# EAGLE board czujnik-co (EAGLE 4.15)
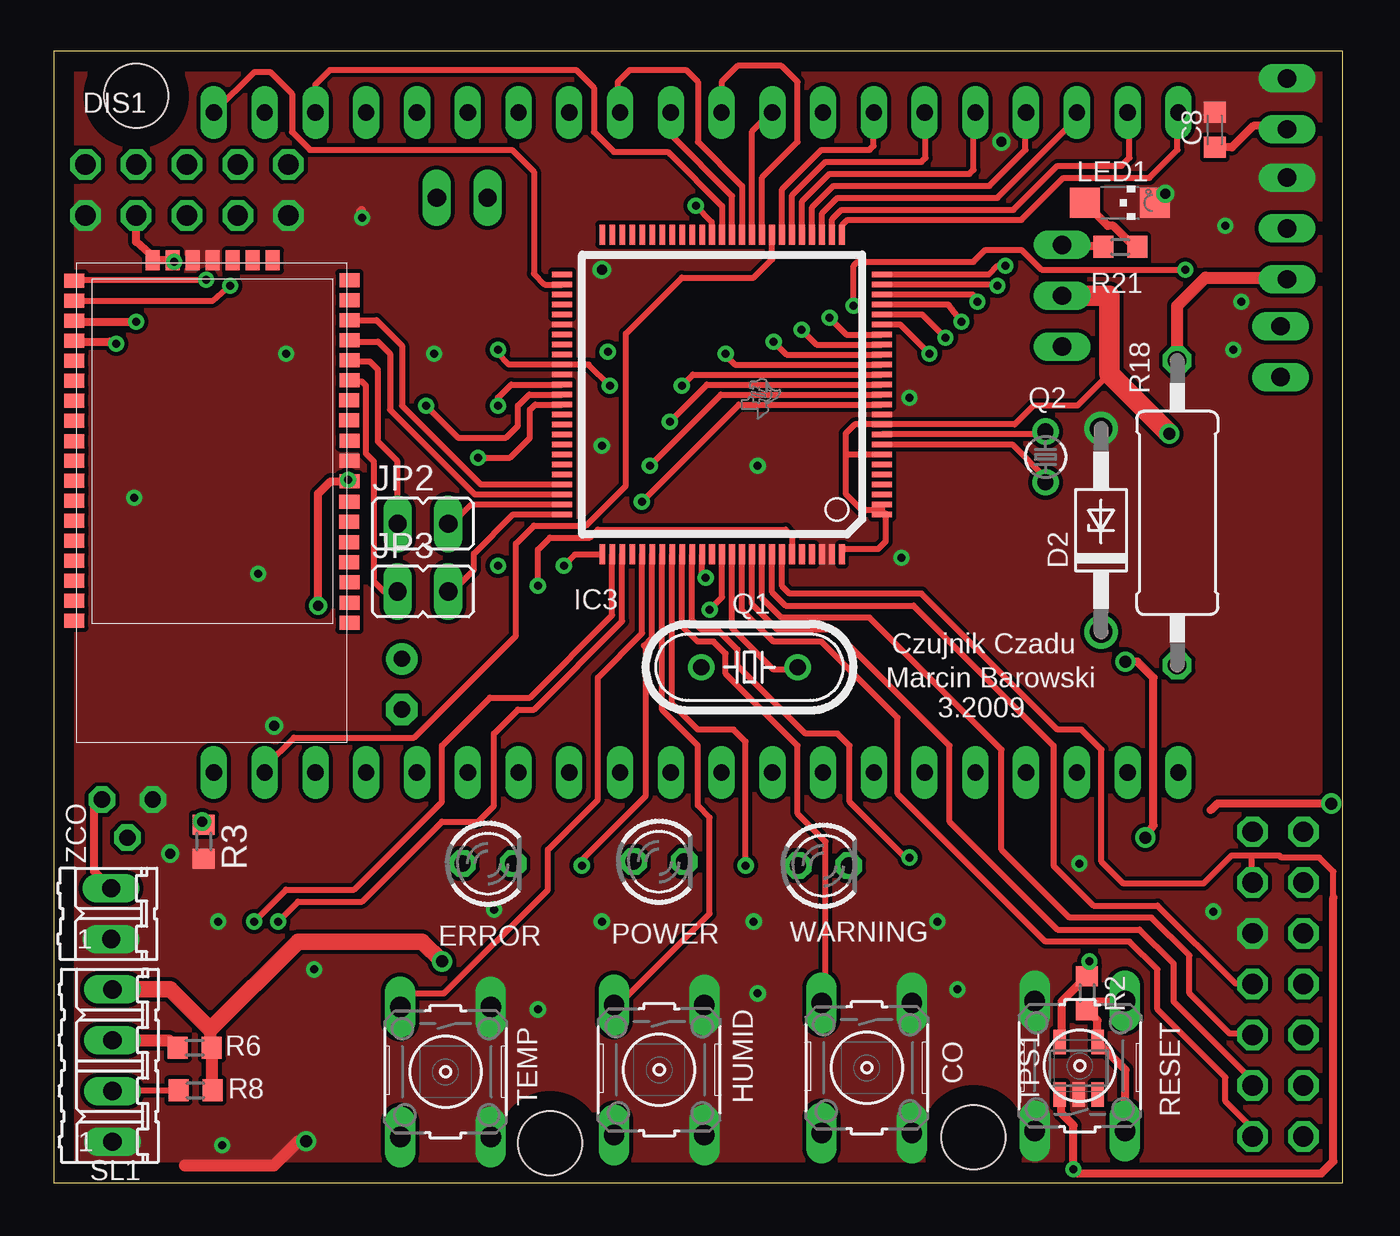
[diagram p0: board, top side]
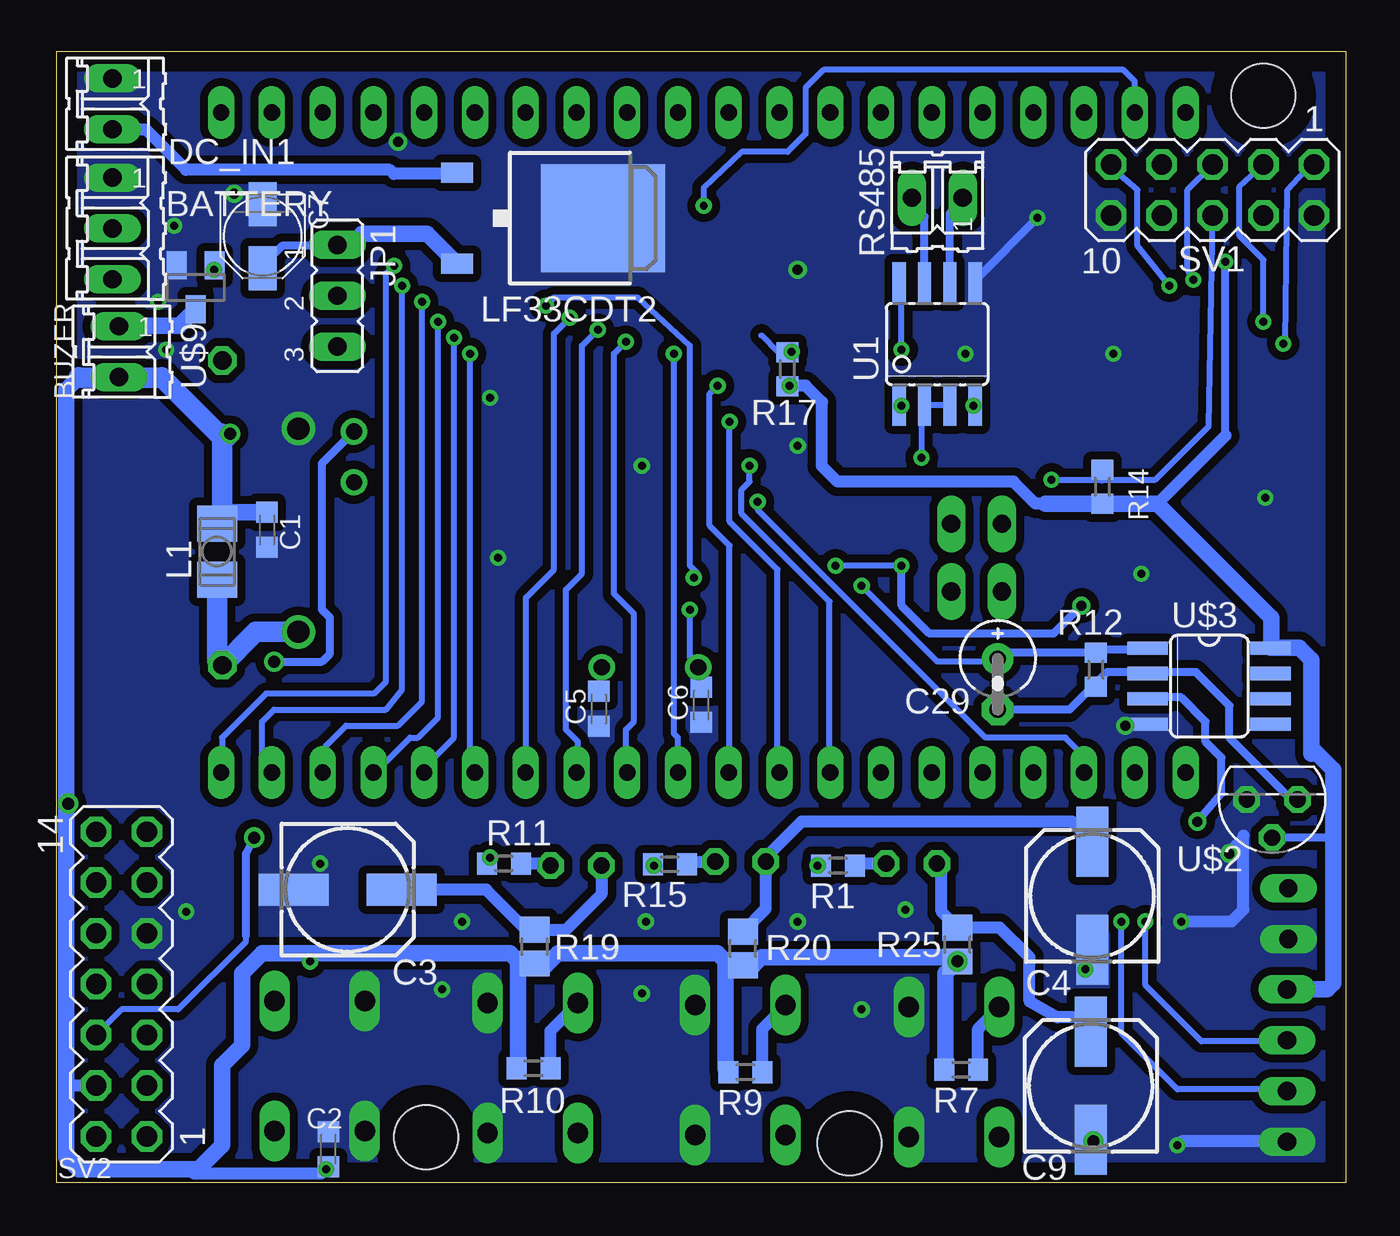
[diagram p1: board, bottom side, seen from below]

Size 64.5 x 56.6 mm. Coordinates in mm from the lower left corner, seen from the top.
Outline: 0,0 64.5,0 64.5,56.6 0,56.6 0,0
Copper layers (1*16): Top 0.035mm / dielectric 1.5mm / Bottom 0.035mm
Design rules "default": minimum track width 10mil, minimum drill 24mil, track to track 8mil, track to pad 8mil, pad to pad 8mil, via to via 8mil, smd to smd 8mil, copper to edge 40mil, drill to drill 8mil, minimum pad ring 10mil, minimum via ring 8mil, stop-mask expansion 4mil, vias tented up to drill 0mil, thermal gap 10mil
Holes 3.2 mm at 4.13,54.37 46.03,2.27 24.83,1.97

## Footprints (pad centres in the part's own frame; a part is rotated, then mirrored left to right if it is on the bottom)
03P = drill 0.914 long: 1 -2.54,0; 2 0,0; 3 2.54,0
02P = drill 0.914 long: 1 -1.27,0; 2 1.27,0
C0603K = smd 1.05 x 1.08: 1 -0.875,0; 2 0.875,0
153CLV-0605 = smd 3.5 x 1.6: + 2.7,0; - -2.7,0
PANASONIC_B = smd 2.2 x 1.4: + 1.6,0; - -1.6,0
E2,5RE = drill 0.813 pad 1.575 round: + -1.27,0 | drill 0.813 pad 1.575 octagon: - 1.27,0
B3F-10XX = drill 1.016 long: 1 -3.251,2.261; 2 3.251,2.261; 3 -3.251,-2.261; 4 3.251,-2.261
DO41Z10 = drill 1.118 round: A 5.08,0; C -5.08,0
H1331C = drill 0.813 long: 1 -24.13,-16.51; 2 -21.59,-16.51; 3 -19.05,-16.51; 4 -16.51,-16.51; 5 -13.97,-16.51; 6 -11.43,-16.51; 7 -8.89,-16.51; 8 -6.35,-16.51; 9 -3.81,-16.51; 10 -1.27,-16.51; 11 1.27,-16.51; 12 3.81,-16.51; 13 6.35,-16.51; 14 8.89,-16.51; 15 11.43,-16.51; 16 13.97,-16.51; 17 16.51,-16.51; 18 19.05,-16.51; 19 21.59,-16.51; 20 24.13,-16.51; 21 24.13,16.51; 22 21.59,16.51; 23 19.05,16.51; 24 16.51,16.51; 25 13.97,16.51; 26 11.43,16.51; 27 8.89,16.51; 28 6.35,16.51; 29 3.81,16.51; 30 1.27,16.51; 31 -1.27,16.51; 32 -3.81,16.51; 33 -6.35,16.51; 34 -8.89,16.51; 35 -11.43,16.51; 36 -13.97,16.51; 37 -16.51,16.51; 38 -19.05,16.51; 39 -21.59,16.51; 40 -24.13,16.51
LED3MM = drill 0.813 octagon: A -1.27,0; K 1.27,0
S-PQFP-G100(PZ) = smd 0.29 x 1: 1 -6,-8; 2 -5.5,-8; 3 -5,-8; 4 -4.5,-8; 5 -4,-8; 6 -3.5,-8; 7 -3,-8; 8 -2.5,-8; 9 -2,-8; 10 -1.5,-8; 11 -1,-8; 12 -0.5,-8; 13 0,-8; 14 0.5,-8; 15 1,-8; 16 1.5,-8; 17 2,-8; 18 2.5,-8; 19 3,-8; 20 3.5,-8; 21 4,-8; 22 4.5,-8; 23 5,-8; 24 5.5,-8; 25 6,-8; 51 6,8; 52 5.5,8; 53 5,8; 54 4.5,8; 55 4,8; 56 3.5,8; 57 3,8; 58 2.5,8; 59 2,8; 60 1.5,8; 61 1,8; 62 0.5,8; 63 0,8; 64 -0.5,8; 65 -1,8; 66 -1.5,8; 67 -2,8; 68 -2.5,8; 69 -3,8; 70 -3.5,8; 71 -4,8; 72 -4.5,8; 73 -5,8; 74 -5.5,8; 75 -6,8 | smd 1 x 0.29: 26 8,-6; 27 8,-5.5; 28 8,-5; 29 8,-4.5; 30 8,-4; 31 8,-3.5; 32 8,-3; 33 8,-2.5; 34 8,-2; 35 8,-1.5; 36 8,-1; 37 8,-0.5; 38 8,0; 39 8,0.5; 40 8,1; 41 8,1.5; 42 8,2; 43 8,2.5; 44 8,3; 45 8,3.5; 46 8,4; 47 8,4.5; 48 8,5; 49 8,5.5; 50 8,6; 76 -8,6; 77 -8,5.5; 78 -8,5; 79 -8,4.5; 80 -8,4; 81 -8,3.5; 82 -8,3; 83 -8,2.5; 84 -8,2; 85 -8,1.5; 86 -8,1; 87 -8,0.5; 88 -8,0; 89 -8,-0.5; 90 -8,-1; 91 -8,-1.5; 92 -8,-2; 93 -8,-2.5; 94 -8,-3; 95 -8,-3.5; 96 -8,-4; 97 -8,-4.5; 98 -8,-5; 99 -8,-5.5; 100 -8,-6
JP2 = drill 0.914 long: 1 -2.54,0; 2 0,0; 3 2.54,0
JP1 = drill 0.914 long: 1 0,-1.27; 2 0,1.27
L3225P = smd 1.8 x 2: 1 -1.4,0; 2 1.4,0
CHIPLED_1206 = smd 1.5 x 1.5: A 0,-1.75; C 0,1.75
DPACK_3 = smd 1 x 1.6: A1 -2.28,-4.8; A2 2.28,-4.8 | smd 5.4 x 6.2: C 0,2.5
HC49/S = drill 0.813 round: 1 -2.413,0; 2 2.413,0
TC26V = drill 0.813 round: 1 -1.27,0; 2 1.27,0
R0603 = smd 1 x 1.1: 1 -0.85,0; 2 0.85,0
0411/15 = drill 0.914 octagon: 1 -7.62,0; 2 7.62,0
R0805 = smd 1.3 x 1.5: 1 -0.85,0; 2 0.85,0
04P = drill 0.914 long: 1 -3.81,0; 2 -1.27,0; 3 1.27,0; 4 3.81,0
MA05-2 = drill 1.016 octagon: 1 -5.08,-1.27; 2 -5.08,1.27; 3 -2.54,-1.27; 4 -2.54,1.27; 5 0,-1.27; 6 0,1.27; 7 2.54,-1.27; 8 2.54,1.27; 9 5.08,-1.27; 10 5.08,1.27
MA07-2 = drill 1.016 octagon: 1 -7.62,-1.27; 2 -7.62,1.27; 3 -5.08,-1.27; 4 -5.08,1.27; 5 -2.54,-1.27; 6 -2.54,1.27; 7 0,-1.27; 8 0,1.27; 9 2.54,-1.27; 10 2.54,1.27; 11 5.08,-1.27; 12 5.08,1.27; 13 7.62,-1.27; 14 7.62,1.27
TSOT23 = smd 0.622 x 1.22: 1 -0.95,-1.31; 2 0,-1.31; 3 0.95,-1.31; 4 0.95,1.31; 5 -0.95,1.31
SOIC08 = smd 0.66 x 2.032: 1 -1.905,-3.073; 2 -0.635,-3.073; 3 0.635,-3.073; 4 1.905,-3.073; 5 1.905,3.073; 6 0.635,3.073; 7 -0.635,3.073; 8 -1.905,3.073
ZIGBIT2 = smd 0.7 x 1: 1 18,0.14; 2 16.99,0.14; 3 15.98,0.14; 4 14.97,0.13; 5 13.96,0.13; 6 12.94,0.13; 7 11.94,0.15; 8 10.92,0.15; 9 9.9,0.15; 10 8.89,0.14; 11 7.88,0.13; 12 6.87,0.13; 13 5.87,0.14; 14 4.87,0.14; 15 3.87,0.14; 16 2.86,0.14; 17 1.86,0.14; 18 0.86,0.14; 26 0.89,-13.62; 27 1.89,-13.62; 28 2.89,-13.62; 29 3.89,-13.62; 30 4.89,-13.62; 31 5.89,-13.62; 32 6.89,-13.62; 33 7.9,-13.62; 34 8.91,-13.62; 35 9.9,-13.62; 36 10.9,-13.62; 37 11.9,-13.62; 38 12.9,-13.62; 39 13.9,-13.62; 40 14.9,-13.62; 41 15.9,-13.62; 42 16.9,-13.62; 43 17.9,-13.62; P$3 11.94,0.13 | smd 1 x 0.7: 19 -0.13,-3.69; 20 -0.13,-4.69; 21 -0.13,-5.7; 22 -0.13,-6.7; 23 -0.13,-7.7; 24 -0.13,-8.7; 25 -0.13,-9.7
TO92 = drill 0.813 octagon: 1 1.27,0; 2 0,1.905; 3 -1.27,0
SO08 = smd 0.66 x 2.032: 1 -1.905,-3.073; 2 -0.635,-3.073; 3 0.635,-3.073; 4 1.905,-3.073; 5 1.905,3.073; 6 0.635,3.073; 7 -0.635,3.073; 8 -1.905,3.073
SOT23 = smd 1 x 1.4: 1 -0.95,-1.1; 2 0.95,-1.1; 3 0,1.1

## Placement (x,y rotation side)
BATTERY  [03P]  61.71,47.74 270 bottom
BUZER  [02P]  61.39,41.57 270 bottom
C1  100n  [C0603K]  53.98,32.66 270 bottom
C2  100n  [C0603K]  50.92,1.68 90 bottom
C3  100u  [153CLV-0605]  49.95,14.66 0 bottom
C4  100u  [153CLV-0605]  12.69,14.35 90 bottom
C5  22p  [C0603K]  37.38,23.71 90 bottom
C6  22p  [C0603K]  32.26,23.91 90 bottom
C7  10uF  [PANASONIC_B]  54.21,47.34 270 bottom
C8  100n  [C0603K]  58.1,52.67 90 top
C9  100u  [153CLV-0605]  12.76,4.85 90 bottom
C29  [E2,5RE]  17.42,24.94 270 bottom
CO  [B3F-10XX]  40.69,5.75 270 top
D2  1N4728  [DO41Z10]  52.41,32.64 90 top
DC_IN1  [02P]  61.71,53.97 270 bottom
DIS1  H1331C  [H1331C]  32.15,37.03 0 top
ERROR  [LED3MM]  21.73,15.97 0 top
HUMID  [B3F-10XX]  30.3,5.65 270 top
IC3  MSP430F449IPZ  [S-PQFP-G100(PZ)]  33.45,39.43 90 top
JP1  [JP2]  50.46,44.37 270 bottom
JP2  [JP1]  18.48,32.96 270 top
JP3  [JP1]  18.48,29.58 270 top
L1  koralik  [L3225P]  56.48,31.57 90 bottom
LED1  [CHIPLED_1206]  53.35,49.01 270 top
LF33CDT2  LF33CDT  [DPACK_3]  39.66,48.25 270 bottom
POWER  [LED3MM]  30.29,16.07 0 top
Q1  [HC49/S]  34.82,25.79 0 top
Q2  [TC26V]  49.63,36.31 270 top
R1  220  [R0603]  25.42,15.87 180 bottom
R2  47k  [R0603]  51.71,9.49 270 top
R3  1k  [R0603]  7.52,17.07 270 top
R6  10k  [R0603]  7.06,6.76 0 top
R7  33k  [R0603]  19.25,5.65 180 bottom
R8  10k  [R0603]  7.1,4.62 0 top
R9  33k  [R0603]  30.05,5.54 180 bottom
R10  33k  [R0603]  40.65,5.73 180 bottom
R11  220  [R0603]  42.13,15.97 0 bottom
R12  1M  [R0603]  12.51,25.66 270 bottom
R14  100k  [R0603]  12.18,34.81 90 bottom
R15  220  [R0603]  33.83,15.94 180 bottom
R17  33k  [R0603]  27.95,40.7 90 bottom
R18  100  [0411/15]  56.22,33.51 270 top
R19  470k  [R0805]  40.6,11.82 270 bottom
R20  470k  [R0805]  30.17,11.72 90 bottom
R21  220  [R0603]  53.37,46.81 0 top
R25  470k  [R0805]  19.44,11.92 90 bottom
RESET  [B3F-10XX]  51.35,5.85 90 top
RS485  [02P]  20.44,49.27 180 bottom
SL1  [04P]  2.94,5.86 90 top
SV1  [MA05-2]  6.67,49.66 180 bottom
SV2  [MA07-2]  61.26,9.94 90 bottom
TEMP  [B3F-10XX]  19.61,5.55 270 top
TPS1  TPS3825  [TSOT23]  51.29,5.73 0 top
U1  SN65HVD10D  [SOIC08]  20.45,41.96 0 bottom
U$1  ZIGBIT_SMD  [ZIGBIT2]  14.66,46.01 270 top
U$2  J177  [TO92]  3.69,19.17 180 bottom
U$3  MCP6042  [SO08]  6.84,24.84 270 bottom
U$9  NDS355AN  [SOT23]  57.55,44.79 180 bottom
WARNING  [LED3MM]  38.52,15.87 0 top
ZCO  [02P]  2.88,13.46 90 top

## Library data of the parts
BATTERY BUZER DC_IN1 RS485 SL1 ZCO = con-amp-quick
C1-C9 C29 L1 R1-R3 R6-R12 R14 R15 R17-R21 R25 = rcl
CO HUMID RESET TEMP = switch-omron
D2 = diode
DIS1 = display-lcd
ERROR LED1 POWER WARNING = led
IC3 = msp430
JP1-JP3 = jumper
LF33CDT2 = linear
Q1 Q2 = crystal
SV1 SV2 = con-lstb
TPS1 = linear-technology-2
U1 = optocoupler
U$1 = zigbit
U$2 = transistor-small-signal
U$3 = maxim
U$9 = transistor

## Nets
1A: DIS1.21 IC3.26
1B: DIS1.20 IC3.25
1C: DIS1.19 IC3.24
1D: DIS1.18 IC3.23
1DP: DIS1.16 IC3.21
1E: DIS1.17 IC3.22
1F: DIS1.22 IC3.27
1G: DIS1.23 IC3.28
2A: DIS1.25 IC3.30
2B: DIS1.24 IC3.29
2C: DIS1.15 IC3.20
2D: DIS1.14 IC3.19
2DP: DIS1.12 IC3.17
2E: DIS1.13 IC3.18
2F: DIS1.26 IC3.31
2G: DIS1.27 IC3.32
3A: DIS1.30 IC3.34
3B: DIS1.29 IC3.35
3C: DIS1.11 IC3.16
3D: DIS1.10 IC3.15
3DP: DIS1.8 IC3.13
3E: DIS1.9 IC3.14
3F: DIS1.31 IC3.37
3G: DIS1.32 IC3.36
:: DIS1.39 IC3.39
_: DIS1.2 IC3.33
A: RS485.2 U1.7
A0: C29.+ IC3.95 R12.1 U$3.1
B: RS485.1 U1.6
BC: DIS1.3 IC3.12
BUZZER: IC3.86 U$9.1
CO: CO.3 IC3.84 R10.1
COM: DIS1.40 IC3.52
ERROR: IC3.81 R1.2
GND: BATTERY.1 C1.2 C2.2 C3.- C4.- C5.1 C6.1 C7.- C8.2 C9.- CO.1 CO.2 D2.A DC_IN1.1 HUMID.1 HUMID.2 IC3.11 IC3.56 IC3.61 IC3.98 IC3.99 LED1.C LF33CDT2.C R3.2 RESET.1 RESET.2 SL1.1 SV1.2 SV1.10 SV2.9 TEMP.1 TEMP.2 TPS1.2 U1.5 U$1.9 U$1.22 U$1.23 U$2.1 U$3.4 U$9.2 ZCO.1
LAD_GND_ON: R17.2
LO_BAT: DIS1.38 IC3.38
N$1: C5.2 IC3.89 Q1.2
N$2: R3.1 U$3.3
N$5: R11.2 WARNING.K
N$6: C6.2 IC3.88 Q1.1
N$8: R2.2 RESET.3 RESET.4 TPS1.4
N$9: BUZER.1 U$9.3
N$11: ERROR.K R1.1
N$13: C29.- R12.2 U$2.3 U$3.2 ZCO.2
N$14: POWER.K R15.1
N$15: C3.+ R19.1 WARNING.A
N$16: IC3.8 Q2.2
N$18: IC3.90 SV2.1
N$19: IC3.91 SV2.3
N$20: LED1.A R21.2
N$21: IC3.92 SV2.5
N$22: IC3.93 SV2.7
N$25: C8.1 DC_IN1.2 LF33CDT2.A1
N$28: D2.C L1.1 R18.2
N$29: C4.+ POWER.A R20.2
N$30: BATTERY.3 R18.1
N$31: C9.+ ERROR.A R25.2
N$32: C7.+ JP1.1 LF33CDT2.A2 R21.1
NMI/RST: IC3.94 SV2.11 TPS1.1
POWER: IC3.83 R15.2
RESET_N: IC3.76 R14.2 SV1.6 U$1.8
RS: IC3.64 U1.2 U1.3
SCL: IC3.77 R6.1 SL1.3
SDA: IC3.78 R8.1 SL1.2
TCK_N: SV1.1 U$1.29
TCLK: IC3.9 Q2.1 SV2.6
TDI_N: SV1.9 U$1.27
TDO_N: SV1.3 U$1.28
TEMP: IC3.80 R7.1 TEMP.3
TMS_N: SV1.5 U$1.26
UART_CTS: IC3.72 U$1.16
UART_RTS: IC3.73 U$1.15
UART_RXD: IC3.74 JP2.2
UART_RXDJ: JP2.1 U$1.14
UART_TXD: IC3.75 JP3.2
UART_TXDJ: JP3.1 U$1.13
URXD: IC3.62 U1.1
UTXD: IC3.63 U1.4
VCC: BUZER.2 C1.1 C2.1 IC3.1 IC3.2 IC3.7 IC3.10 IC3.60 IC3.100 JP1.2 L1.2 R2.1 R6.2 R7.2 R8.2 R9.2 R10.2 R14.1 R17.1 R19.2 R20.1 R25.1 SL1.4 SV1.4 SV2.4 TPS1.5 U1.8 U$1.24 U$1.25 U$2.2 U$3.8
WARNING: IC3.85 R11.1
WILG: HUMID.3 IC3.82 R9.1

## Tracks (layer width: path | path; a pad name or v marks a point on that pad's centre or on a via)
1A
  Top 0.305: DIS1.21 56.28,53.52 56.23,53.47 56.23,51.67 54.83,50.27 50.53,50.27 48.43,48.17 39.73,48.17 39.45,47.89 IC3.26
1B  (via drill 0.4)
  Top 0.305: IC3.25 46.79,45.43 47.23,45.87 v47.63,45.87
  Bottom 0.305: v47.63,45.87 48.03,45.47 48.03,25.07 48.63,24.47 54.03,24.47 56.23,22.27 56.23,20.67 56.28,20.62 DIS1.20
1C  (via drill 0.4)
  Top 0.305: IC3.24 47.17,44.93 arc-90 v47.23,44.87
  Bottom 0.305: v47.23,44.87 47.23,24.67 48.03,23.67 53.63,23.67 54.23,23.07 54.23,20.87 53.83,20.47 53.78,20.52 DIS1.19
1D  (via drill 0.4)
  Top 0.305: IC3.23 45.99,44.43 v46.23,44.07
  Bottom 0.305: v46.23,44.07 46.23,24.07 47.43,22.87 50.03,22.87 51.03,21.87 51.03,20.67 51.18,20.52 DIS1.18
1DP  (via drill 0.4)
  Top 0.305: IC3.21 43.47,43.43 v44.63,42.27
  Bottom 0.305: DIS1.16 46.12,20.56 46.23,20.67 44.63,22.27 v44.63,42.27
1E  (via drill 0.4)
  Top 0.305: IC3.22 44.77,43.93 v45.43,43.07
  Bottom 0.305: v45.43,43.07 45.43,23.27 46.43,22.27 46.83,22.27 48.63,20.47 48.66,20.5 DIS1.17
1F
  Top 0.305: IC3.27 38.95,48.19 39.43,48.67 48.03,48.67 50.23,50.87 53.43,50.87 53.83,51.27 53.83,53.47 53.76,53.54 DIS1.22
1G
  Top 0.305: IC3.28 38.45,48.49 39.23,49.27 47.23,49.27 51.23,53.27 51.2,53.3 DIS1.23
2A
  Top 0.305: IC3.30 37.45,49.09 38.83,50.47 45.83,50.47 46.03,50.67 46.03,53.47 46.1,53.54 DIS1.25
2B
  Top 0.305: IC3.29 37.95,48.79 39.03,49.87 46.83,49.87 48.63,51.67 48.63,53.47 48.66,53.5 DIS1.24
2C  (via drill 0.4)
  Top 0.305: IC3.20 42.37,42.93 v43.83,41.47
  Bottom 0.305: v43.83,41.47 43.83,20.87 43.58,20.62 DIS1.15
2D  (via drill 0.4)
  Top 0.305: IC3.19 39.67,42.43 v38.83,43.27
  Bottom 0.305: v38.83,43.27 39.63,42.47 39.63,30.67 41.03,29.27 41.03,20.67 41.04,20.66 DIS1.14
2DP  (via drill 0.4)
  Top 0.305: IC3.17 36.67,41.43 v36.03,42.07
  Bottom 0.305: v36.03,42.07 36.63,41.47 36.63,29.47 35.63,28.47 35.63,23.07 36.03,22.67 36.03,20.47 35.98,20.52 DIS1.12
2E  (via drill 0.4)
  Top 0.305: IC3.18 38.17,41.93 v37.43,42.67
  Bottom 0.305: v37.43,42.67 38.23,41.87 38.23,30.47 39.03,29.67 39.03,22.67 38.43,22.07 38.43,20.47 38.48,20.52 DIS1.13
2F
  Top 0.305: IC3.31 36.95,49.39 38.63,51.07 43.43,51.07 43.63,51.27 43.63,53.27 43.58,53.32 DIS1.26
2G
  Top 0.305: IC3.32 36.45,49.69 38.43,51.67 40.83,51.67 41.03,51.87 41.03,53.47 41.04,53.48 DIS1.27
3A
  Top 0.305: IC3.34 35.45,50.29 37.23,52.07 37.23,55.07 36.43,55.87 34.23,55.87 33.43,55.07 DIS1.30 | DIS1.30 33.43,53.47 | DIS1.30
3B
  Top 0.305: DIS1.29 35.9,53.54 34.95,52.59 IC3.35
3C  (via drill 0.4)
  Top 0.305: IC3.16 34.09,40.93 33.63,41.39 v33.63,41.47
  Bottom 0.305: 33.63,37.47 33.63,22.47 33.43,22.27 DIS1.11 | 33.63,37.47 33.63,37.67 | 33.63,37.47 v33.63,41.47
3D  (via drill 0.4)
  Top 0.305: IC3.15 31.99,40.43 v31.43,39.87
  Bottom 0.305: DIS1.10 30.83,20.47 30.83,31.87 31.83,32.87 31.83,39.47 v31.43,39.87
3DP  (via drill 0.4)
  Top 0.305: IC3.13 33.39,39.43 v29.83,35.87
  Bottom 0.305: v29.83,35.87 29.83,35.07 30.23,34.67 30.23,33.47 25.83,29.07 25.83,20.87 26.03,20.67 25.88,20.52 DIS1.8
3E  (via drill 0.4)
  Top 0.305: IC3.14 32.69,39.93 v30.83,38.07
  Bottom 0.305: v30.83,38.07 30.83,33.07 28.43,30.67 28.43,20.67 28.34,20.58 DIS1.9
3F
  Top 0.305: IC3.37 33.95,49.35 30.83,52.47 30.83,53.47 30.88,53.52 DIS1.31
3G
  Top 0.305: IC3.36 34.45,49.85 32.23,52.07 32.23,55.07 31.63,55.67 28.83,55.67 28.23,55.07 28.23,53.67 28.34,53.56 DIS1.32
:  (via drill 0.4)
  Top 0.305: IC3.39 32.93,47.45 32.93,48.07 v32.13,48.87
  Bottom 0.305: DIS1.39 10.56,55.1 11.13,55.67 26.13,55.67 27.03,54.77 27.03,52.47 27.93,51.57 30.23,51.57 32.13,49.77 v32.13,48.87
_
  Top 0.305: IC3.33 35.95,46.19 35.03,45.27 31.43,45.27 28.63,42.47 28.63,34.87 26.63,32.87 24.03,32.87 23.13,31.97 23.13,27.37 18.03,22.27 12.03,22.27 10.56,20.8 DIS1.2
A
  Bottom 0.406: RS485.2 21.71,49.19 21.83,49.07 21.08,48.32 U1.7
A0  (via drill 0.4)
  Top 0.305: IC3.95 36.95,32.35 36.63,32.67 27.23,32.67 26.83,32.27 24.83,32.27 24.23,31.67 v24.23,29.87
  Bottom 0.305: v24.23,29.87 20.43,26.07 17.63,26.07 17.43,26.27 17.42,26.26 C29.+
  Bottom 0.406: 10.23,26.67 10.12,26.67 | 10.23,26.67 12.43,26.67 12.43,26.59 R12.1 17.39,26.51 17.43,26.47 17.42,26.46 C29.+ | U$3.1 10.23,26.74 10.23,26.67
B
  Bottom 0.406: RS485.1 19.03,49.27 19.81,48.49 U1.6
BC  (via drill 0.4)
  Top 0.305: IC3.12 34.29,38.93 v29.43,34.07
  Bottom 0.305: v29.43,34.07 29.43,33.67 18.03,22.27 14.03,22.27 13.23,21.47 13.23,20.47 13.18,20.52 DIS1.3
BUZZER  (via drill 0.4)
  Top 0.305: IC3.86 32.45,30.45 v32.63,30.27 | v56.63,45.67 49.43,45.67 48.43,46.67 46.63,46.67 46.03,46.07 40.23,46.07 40.03,45.87 v40.03,43.87
  Bottom 0.305: v32.63,30.27 32.43,30.47 32.83,30.87 32.83,41.87 35.43,44.27 39.63,44.27 v40.03,43.87 | U$9.1 56.63,45.86 v56.63,45.67
CO
  Top 0.305: CO.3 38.63,9.2 38.63,17.07 37.23,18.47 37.23,21.87 33.63,25.47 33.63,26.47 33.03,27.07 32.23,27.07 31.45,27.85 IC3.84
  Bottom 0.61: CO.3 38.43,8.97 39.8,7.6 R10.1
COM
  Top 0.305: DIS1.40 10.05,55.57 10.83,55.57 11.93,54.47 11.93,52.57 12.83,51.67 22.93,51.67 24.03,50.57 24.03,45.47 24.57,44.93 IC3.52
ERROR  (via drill 0.4)
  Top 0.305: IC3.81 29.95,27.29 29.53,26.87 29.63,26.77 29.63,19.37 26.43,16.17 v26.43,15.87
  Bottom 0.305: 26.23,15.87 R1.2 v26.43,15.87
GND  (via drill 0.4, 0.5, 0.6)
  Top 0.406: 15.36,48.6 15.43,48.67 v15.43,48.27
  Top 0.61: 6.57,0.87 11.03,0.87 12.23,2.07 v12.63,2.07 | v8.43,1.87 8.48,1.87 | v8.23,13.07 8.26,13.04
  Bottom 0.406: U1.5 18.54,45.15 v15.43,48.27 | v5.83,16.47 5.83,16.67 5.13,17.37
  Bottom 0.61: C9.- 12.83,2.08 12.83,1.87 v12.63,2.07 | SL1.1 2.96,2.07 8.23,2.07 v8.43,1.87 | v8.23,13.07 5.73,13.07 5.13,13.67 5.13,17.37
  other vias: 13.03,10.67 22.03,13.67 27.43,13.07 19.03,41.47 11.63,41.47 4.03,34.27 10.23,30.47 27.43,45.67 24.23,8.67 35.03,13.07 35.23,9.47 44.23,13.07 45.23,9.67 58.03,13.57 51.33,15.97 58.63,47.87 59.03,41.67 59.43,44.07 42.43,31.27 35.23,35.87 27.43,36.87 42.83,39.27 55.63,49.47 47.43,52.07 11.03,22.87
  pour Top (rank 6, no thermals): 0.23,56.47 64.43,56.47 64.43,53.47 64.43,0.07 0.03,0.07 0.03,56.47
  pour Bottom (isolate 0.406, rank 6, no thermals): 0.03,56.47 64.43,56.47 64.43,0.07 60.43,0.07 0.03,0.07
LAD_GND_ON  (via drill 0.4)
  Top 0.305: v27.73,41.57 27.59,41.43
  Bottom 0.305: 29.25,42.39 28.41,41.55 28.39,41.57 v27.73,41.57 27.93,41.57 R17.2
LO_BAT
  Top 0.305: IC3.38 33.45,48.85 30.83,51.47 30.73,51.57 28.03,51.57 27.03,52.57 27.03,54.77 26.13,55.67 13.83,55.67 13.1,54.94 DIS1.38
N$1
  Top 0.305: IC3.89 33.95,27.75 36.03,25.67 37.23,25.67 Q1.2
  Bottom 0.305: Q1.2 37.25,25.77 37.33,25.77 37.33,24.63 C5.2
N$2  (via drill 0.5)
  Top 0.406: R3.1 7.48,17.92 7.43,17.87 v7.43,18.07
  Bottom 0.406: v7.43,18.07 6.23,19.47 6.23,21.27 7.03,22.07 7.03,23.07 8.24,24.27 10.03,24.27 10.03,24.21 U$3.3
N$5
  Bottom 0.61: WARNING.K 39.83,15.87 39.93,15.97 R11.2
N$6  (via drill 0.4)
  Top 0.305: IC3.88 33.45,29.29 v32.83,28.67
  Bottom 0.305: v32.83,28.67 32.83,26.27 32.41,25.85 Q1.1 32.43,25.77 32.43,24.96 C6.2
N$8
  Top 0.406: RESET.4 53.63,9.08 53.63,9.07 52.14,9.07 R2.2 52.23,8.12 TPS1.4 53.63,5.65 53.63,2.62 RESET.3
N$9
  Bottom 0.406: 57.55,43.75 57.43,43.87 | 57.55,43.75 U$9.3 | BUZER.1 58.46,42.84 57.55,43.75
  Bottom 0.813: U$9.3 58.37,42.87 61.43,42.87
N$11
  Bottom 0.61: R1.1 24.43,15.87 24.33,15.97 ERROR.K
N$13
  Top 0.406: U$2.3 2.12,18.87 2.03,18.87 2.03,15.58 ZCO.2
  Bottom 0.406: 12.63,24.87 12.57,24.81 R12.2 | 12.63,24.87 11.96,25.54 9.83,25.54 9.83,25.48 | 12.63,24.87 13.83,23.67 C29.- | U$2.3 2.43,19.27 2.83,19.27 5.83,22.27 5.83,23.87 7.5,25.54 10.03,25.54 10.03,25.48 | 9.83,25.48 9.83,25.47 | 9.83,25.48 U$3.2 10.03,25.48 | 10.03,25.48 10.03,25.47
N$14
  Bottom 0.61: R15.1 32.98,15.92 32.93,15.87 32.73,16.07 POWER.K
N$15
  Bottom 0.61: WARNING.A 37.25,15.69 37.23,15.67 37.23,14.47 39.03,12.67 R19.1 41.03,12.67 43.02,14.66 C3.+
N$16
  Top 0.305: Q2.2 49.63,35.27 47.97,36.93 IC3.8
N$18
  Top 0.305: IC3.90 34.45,28.65 36.03,27.07 38.43,27.07 42.23,23.27 42.23,19.47 49.63,12.07 53.83,12.07 55.23,10.67 55.23,8.67 58.63,5.27 58.63,4.07 59.93,2.77 59.93,2.37 59.94,2.37 SV2.1
N$19
  Top 0.305: IC3.91 34.95,28.95 36.23,27.67 39.03,27.67 44.83,21.87 44.83,18.07 50.23,12.67 54.33,12.67 56.03,10.97 56.03,9.07 59.93,5.17 59.93,4.87 SV2.3
N$20
  Top 0.406: LED1.A 52.74,47.87 53.03,47.87 54.08,46.82 R21.2
N$21
  Top 0.305: IC3.92 35.45,29.25 36.43,28.27 40.83,28.27 47.43,21.67 47.43,16.67 50.83,13.27 54.93,13.27 56.83,11.37 56.83,9.47 58.83,7.47 59.93,7.47 59.93,7.46 SV2.5
N$22
  Top 0.305: IC3.93 35.95,29.55 36.63,28.87 43.03,28.87 50.03,21.87 50.03,15.87 52.03,13.87 55.23,13.87 59.13,9.97 59.96,9.97 SV2.7
N$25
  Top 0.406: C8.1 58.96,51.79 60.03,52.87 61.83,52.87 61.83,52.82 DC_IN1.2
  Bottom 0.61: DC_IN1.2 61.68,52.67 60.03,52.67 58.03,50.67 47.83,50.67 47.63,50.47 44.52,50.47 LF33CDT2.A1
  Bottom 0.813: 61.83,52.67 61.8,52.7 DC_IN1.2
N$28
  Bottom 1.016: D2.C 54.54,27.56 R18.2 56.23,25.87 56.48,26.12 L1.1
N$29
  Bottom 0.61: R20.2 29.03,13.71 POWER.A 29.02,16.26 29.03,16.27 27.23,18.07 13.71,18.07 C4.+
N$30
  Top 0.61: R18.1 56.22,43.86 57.63,45.27 61.63,45.27 BATTERY.3
N$31
  Bottom 0.61: ERROR.A 20.36,15.87 20.23,15.87 20.23,13.56 R25.2 17.33,12.77 15.83,11.27 15.83,9.07 14.43,8.27 12.83,8.27 | C9.+ 12.76,7.6 12.83,7.67 12.83,8.27 | 12.83,8.27 12.83,8.87 | 12.83,8.27 12.63,8.27
N$32
  Top 0.406: R21.1 52.46,46.87 50.5,46.87 JP1.1
  Bottom 0.406: C7.+ 54.21,45.89 53.23,46.87 50.63,46.87 50.59,46.91 JP1.1
  Bottom 0.813: LF33CDT2.A2 45.96,47.47 49.23,47.47 49.83,46.87 50.43,46.87 50.43,46.88 JP1.1
NMI/RST  (via drill 0.4)
  Top 0.305: IC3.94 36.45,29.85 36.83,29.47 43.43,29.47 50.23,22.67 51.43,22.67 52.43,21.67 52.43,16.07 53.53,14.97 57.53,14.97 58.93,16.37 59.93,16.37 | SV2.11 59.93,15.08 59.93,16.37 | 64.03,14.27 64.03,15.57 63.33,16.27 61.43,16.27 61.33,16.37 59.93,16.37
  Top 0.406: 64.03,14.27 64.03,1.07 63.43,0.47 51.23,0.47 v51.03,0.67 51.03,2.87 50.43,3.47 50.43,4.33 TPS1.1
  Bottom 0.406: 50.83,0.72 50.83,0.67 v51.03,0.67
POWER  (via drill 0.4)
  Top 0.305: IC3.83 30.95,23.95 32.23,22.67 34.03,22.67 34.63,22.07 v34.63,15.87
  Bottom 0.305: v34.63,15.87 34.68,15.92 R15.2
RESET_N  (via drill 0.4, 0.5)
  Top 0.305: U$1.8 14.81,35.15 14.83,35.17 v14.73,35.17 | IC3.76 26.09,31.43 v25.53,30.87
  Top 0.406: U$1.8 13.85,35.09 13.23,34.47 v13.23,28.87
  Bottom 0.305: SV1.6 6.87,37.83 9.53,35.17 12.23,35.17 v14.73,35.17 | v22.23,30.87 v25.53,30.87
  Bottom 0.406: R14.2 12.23,35.66 12.23,35.17 | v13.23,28.87 14.63,27.47 20.83,27.47 22.23,28.87 v22.23,30.87
RS  (via drill 0.4)
  Top 0.305: IC3.64 24.09,38.93 23.83,38.67 23.83,37.27 22.83,36.27 v21.23,36.27
  Bottom 0.305: v21.23,36.27 21.23,38.67 21.03,38.87 21.05,38.89 U1.2 20.05,38.89 20.03,38.87 20.01,38.89 U1.3
SCL  (via drill 0.4)
  Top 0.305: IC3.77 27.95,28.39 23.83,24.27 21.83,24.27 19.43,21.87 19.43,19.07 15.03,14.67 11.63,14.67 v10.03,13.07
  Top 0.61: R6.1 6.14,6.76 5.77,7.13 SL1.3
  Bottom 0.305: SL1.3 3,7.07 7.23,7.07 10.03,9.87 v10.03,13.07
SDA  (via drill 0.4)
  Top 0.305: IC3.78 28.45,28.09 24.03,23.67 23.23,23.67 22.03,22.47 22.03,18.87 21.23,18.07 19.43,18.07 15.43,14.07 12.23,14.07 v11.23,13.07 | SL1.2 3.03,4.67 3.08,4.62 R8.1
  Bottom 0.305: v11.23,13.07 11.23,7.47 8.43,4.67 3.03,4.67 SL1.2
TCK_N  (via drill 0.4)
  Top 0.305: 2.83,42.07 3.03,42.07 v3.13,41.97
  Top 0.406: U$1.29 1.09,42.07 2.83,42.07
  Bottom 0.305: v3.13,41.97 3.03,42.07 2.93,49.67 1.77,50.93 | 1.77,50.93 1.73,50.97 | 1.77,50.93 SV1.1
TCLK  (via drill 0.6)
  Top 0.305: Q2.1 49.63,37.67 49.39,37.43 IC3.9
  Top 0.406: v53.63,26.07 54.23,26.07 55.03,25.27 55.03,17.87 v54.63,17.27
  Bottom 0.305: 55.03,12.36 55.03,12.07 58.43,8.67 61.26,8.67 SV2.6
  Bottom 0.406: Q2.1 51.23,35.98 51.23,28.67 50.83,28.27 50.83,26.47 51.23,26.07 v53.63,26.07 | 55.03,12.36 55.03,16.47 v54.63,17.27
TDI_N  (via drill 0.4)
  Top 0.305: U$1.27 7.98,44.12 v8.83,44.87
  Bottom 0.305: v8.83,44.87 10.43,46.87 10.43,49.67 11.79,50.83 | 11.79,50.83 11.73,50.87 | 11.79,50.83 SV1.9
TDO_N  (via drill 0.4)
  Top 0.406: U$1.28 1.09,43.07 v4.13,43.07
  Bottom 0.305: SV1.3 5.33,49.83 5.33,47.37 4.13,46.17 v4.13,43.07
TEMP
  Top 0.305: IC3.80 29.45,27.49 27.23,25.27 27.23,19.17 24.73,16.67 24.73,14.67 19.53,9.47 17.93,9.47 17.35,8.89 | 17.35,8.89 17.33,8.87 17.35,8.85 TEMP.3 17.35,8.89
  Bottom 0.61: 17.3,8.8 17.23,8.87 | 17.3,8.8 TEMP.3 | R7.1 18.4,7.7 17.3,8.8
TMS_N  (via drill 0.4)
  Top 0.305: U$1.26 1.08,45.12 1.13,45.07 1.23,45.17 v7.63,45.17
  Bottom 0.305: SV1.5 7.93,49.67 7.93,45.67 7.83,45.47 v7.63,45.17
UART_CTS
  Top 0.305: U$1.16 16.15,43.15 17.43,41.87 17.43,38.87 21.37,34.93 IC3.72
UART_RTS
  Top 0.305: IC3.73 21.07,34.43 16.83,38.67 16.83,41.47 16.23,42.07 14.83,42.07 14.83,42.11 U$1.15
UART_RXD
  Top 0.305: JP2.2 19.83,32.87 20.89,33.93 IC3.74
UART_RXDJ
  Top 0.305: JP2.1 17.21,36.09 16.23,37.07 16.23,40.67 15.83,41.07 14.83,41.07 14.8,41.1 U$1.14
UART_TXD
  Top 0.305: IC3.75 22.99,33.43 21.03,31.47 21.03,30.67 19.83,29.47 19.75,29.55 JP3.2
UART_TXDJ
  Top 0.305: JP3.1 16.52,29.58 16.03,30.07 16.03,36.07 15.63,36.47 15.63,39.87 15.43,40.07 14.83,40.07 14.8,40.1 U$1.13
URXD  (via drill 0.4)
  Top 0.305: IC3.62 22.89,39.93 22.23,39.27 v22.23,38.87
  Bottom 0.305: U1.1 22.41,38.89 22.43,38.87 v22.23,38.87
UTXD  (via drill 0.4)
  Top 0.305: IC3.63 23.79,39.43 23.23,38.87 23.23,37.87 22.63,37.27 20.23,37.27 v18.63,38.87
  Bottom 0.305: U1.4 18.54,38.99 18.63,39.07 v18.63,38.87
VCC  (via drill 0.4, 0.6)
  Top 0.305: 39.63,36.47 39.63,34.47 40.43,33.67 41.23,33.67 | 39.63,36.47 39.63,37.47 40.09,37.93 IC3.10 48.09,37.93 49.03,38.87 51.23,38.87 52.63,40.27 52.63,43.87 52.83,44.07 52.83,44.37 | 41.23,33.67 41.45,33.45 IC3.1 41.59,33.43 41.63,33.47 41.63,32.07 41.25,31.69 39.45,31.69 IC3.100 | 41.23,33.67 41.45,33.89 IC3.2 41.45,33.69 | IC3.7 39.67,36.43 39.63,36.47 | v6.03,46.07 6.03,46.27 | v22.23,41.67 22.23,41.47 22.77,40.93 IC3.60 26.77,40.93 v27.83,39.87 | 50.23,44.27 50.33,44.37 JP1.2
  Top 0.406: SV1.4 4.13,47.07 5.03,46.27 4.96,46.2 U$1.25 5.9,46.14 5.96,46.2 | 6.03,46.27 5.96,46.2 | 5.96,46.2 U$1.24 | TPS1.5 50.37,7.07 50.43,7.07 50.43,9.06 R2.1 51.71,10.95 v51.83,11.07 | 57.9,18.64 58.23,18.97 v63.93,18.97
  Top 0.61: 7.83,7.67 7.83,6.87 7.91,6.79 R6.2 7.91,4.75 7.83,4.67 7.88,4.62 R8.2
  Top 0.813: SL1.4 5.83,9.67 7.83,7.67 12.23,12.07 18.43,12.07 v19.43,11.07
  Top 1.016: JP1.2 52.83,44.37 52.83,40.47 v55.83,37.47
  Bottom 0.305: U1.8 22.32,45.07 22.23,45.07 v22.23,41.67 | 28.03,39.87 28.23,39.87 | SV2.4
  Bottom 0.406: 6.03,37.37 v6.03,46.07 | 51.83,11.47 v51.83,11.07 | 64.13,18.97 64.03,18.97 v63.93,18.97 | U$2.2 0.63,17.27 | 11.03,33.97 11.03,33.96 | 11.03,33.96 R14.1 | 11.03,33.96 11.03,33.87 | 2.63,26.77 2.63,26.74 | 2.63,26.74 U$3.8 3.83,26.74 | 2.63,26.74 2.63,26.67 | 3.83,26.87 3.77,26.87 | 3.83,26.87 3.83,27.87 | 3.83,26.74 3.83,26.67 | 3.83,26.74 3.83,26.87
  Bottom 0.61: 9.43,33.97 6.03,37.37 | 3.77,26.87 3.73,26.87 | SL1.4 3.13,9.67 | R17.1 27.97,39.87 28.03,39.87 v27.83,39.87 27.03,39.87 26.21,39.05 26.21,35.87 26.23,35.87 25.43,35.07 16.63,35.07 15.53,33.97 15.03,33.97 | 64.03,4.87 SV2.4 | 57.63,0.67 57.63,0.47 51.26,0.47 C2.1
  Bottom 0.813: 30.93,10.97 30.83,10.87 R20.1 29.63,10.87 29.23,11.27 19.63,11.27 v19.43,11.07 R25.1 20.03,10.48 20.03,5.67 20.08,5.67 R7.2 | 30.93,10.97 31.43,11.47 39.43,11.47 40.03,10.87 40.63,10.87 40.6,10.9 R19.2 41.33,10.97 41.43,11.07 | 41.43,11.07 41.83,11.47 51.83,11.47 54.23,11.47 55.23,10.47 55.23,6.87 56.23,5.87 56.23,5.17 | 30.93,10.97 31.03,10.87 31.03,5.67 R9.2 | R10.2 41.43,5.8 41.43,11.07 | C1.1 55.97,33.54 56.23,33.27 | 15.03,33.97 11.03,33.97 9.43,33.97 3.73,28.27 3.73,26.87 | 1.73,21.67 1.73,21.46 | 1.73,21.67 1.73,26.17 2.33,26.77 2.63,26.77 3.78,26.77 | SL1.4 0.93,9.67 0.63,9.97 0.63,17.27 0.63,20.67 1.63,21.67 1.73,21.67 | 63.4,40.3 64.03,39.67 64.03,18.97 64.03,4.87 64.03,1.27 63.43,0.67 57.63,0.67 57.43,0.67 56.23,1.87 56.23,5.17 | 56.23,5.17 56.23,5.47
  Bottom 1.016: 56.23,37.27 59.26,40.3 59.29,40.27 61.36,40.27 BUZER.2 61.42,40.27 63.37,40.27 63.4,40.3 | L1.2 56.48,33.02 56.23,33.27 56.23,37.07 | 56.23,37.27 56.23,37.07 | 56.23,37.27 56.23,37.47 | 56.23,37.07 v55.83,37.47
WARNING  (via drill 0.4)
  Top 0.305: v42.83,16.27 42.63,16.27 39.83,19.07 39.83,21.87 39.23,22.47 37.63,22.47 34.23,25.87 34.23,26.67 33.23,27.67 32.43,27.67 31.95,28.15 IC3.85
  Bottom 0.305: R11.1 42.98,16.12 v42.83,16.27
WILG
  Top 0.305: IC3.82 30.45,23.65 32.23,21.87 32.23,18.87 32.83,18.27 32.83,13.47 28.43,9.07 28.21,9.07 HUMID.3
  Bottom 0.61: HUMID.3 28.04,8.86 29.2,7.7 R9.1

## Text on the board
tPlace: Czujnik Czadu | Marcin Barowski | 3.2009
